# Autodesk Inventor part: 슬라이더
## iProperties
Company: 한국ATC센터
Created: 2015-04
Part Number: 슬라이더
Document SubType Name: Modeling
Designer: KYOUNG IL JANG
Density: 1 g/cm^3
Material: 기본값
Mass: 11.2119 g
Surface Area: 38.892 cm^2
Volume: 11.2119 cm^3
Author: KYOUNG IL JANG
